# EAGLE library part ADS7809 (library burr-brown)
16-Bit 10us Serial CMOS Sampling ADC
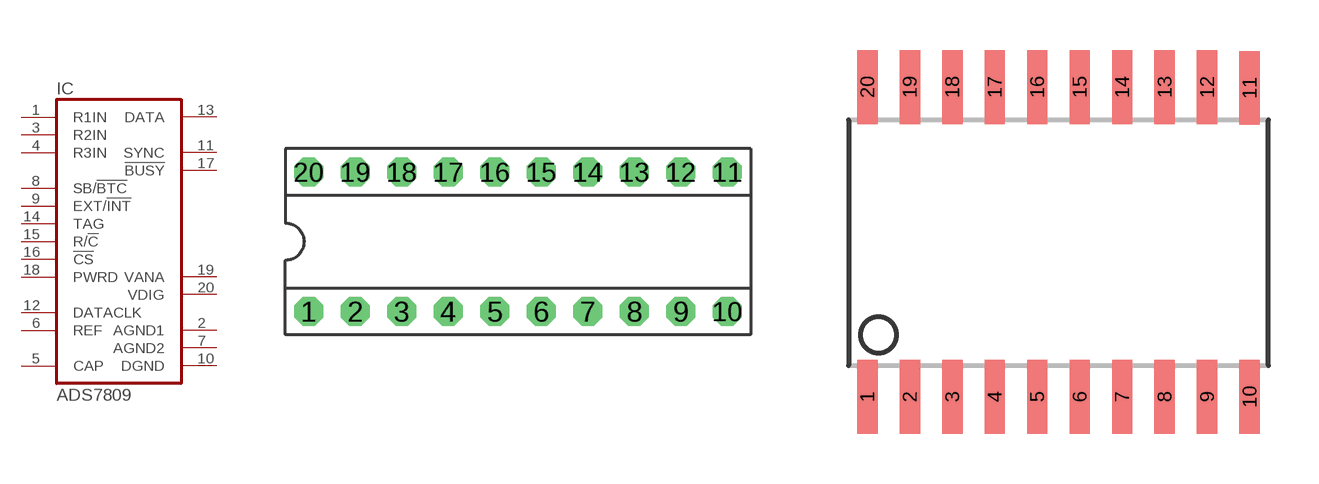
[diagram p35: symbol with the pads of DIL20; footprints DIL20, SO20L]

Designator prefix IC

## ADS7809P (MF: ALTERA CORPORATION; MPN: AD977ANZ; OC_FARNELL: 1079312; OC_NEWARK: 59K7418)  [DIL20]
1  R1IN  in
2  AGND1  pwr
3  R2IN  in
4  R3IN  in
5  CAP  pas
6  REF
7  AGND2  pwr
8  SB/!BTC  in
9  EXT/!INT  in
10  DGND  pwr
11  SYNC  out
12  DATACLK
13  DATA  out
14  TAG  in
15  R/!C  in
16  !CS  in
17  !BUSY  out
18  PWRD  in
19  VANA  pwr
20  VDIG  pwr

## ADS7809U (MF: TEXAS INSTRUMENTS; MPN: ADS7809U; OC_FARNELL: 1214386; OC_NEWARK: 80K5549)  [SO20L]
Pads as for DIL20

## Footprint DIL20 (pad centres in mm)
Dual In Line
drill 0.813 pad 1.6 octagon: 1 -11.43,-3.81; 2 -8.89,-3.81; 3 -6.35,-3.81; 4 -3.81,-3.81; 5 -1.27,-3.81; 6 1.27,-3.81; 7 3.81,-3.81; 8 6.35,-3.81; 9 8.89,-3.81; 10 11.43,-3.81; 11 11.43,3.81; 12 8.89,3.81; 13 6.35,3.81; 14 3.81,3.81; 15 1.27,3.81; 16 -1.27,3.81; 17 -3.81,3.81; 18 -6.35,3.81; 19 -8.89,3.81; 20 -11.43,3.81

## Footprint SO20L (pad centres in mm)
Small Outline Package, large
smd 0.61 x 2.21: 1 -5.715,-4.636; 2 -4.445,-4.636; 3 -3.175,-4.636; 4 -1.905,-4.636; 5 -0.635,-4.636; 6 0.635,-4.636; 7 1.905,-4.636; 8 3.175,-4.636; 9 4.445,-4.636; 10 5.715,-4.636; 11 5.715,4.61; 12 4.445,4.636; 13 3.175,4.636; 14 1.905,4.636; 15 0.635,4.636; 16 -0.635,4.636; 17 -1.905,4.636; 18 -3.175,4.636; 19 -4.445,4.636; 20 -5.715,4.636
